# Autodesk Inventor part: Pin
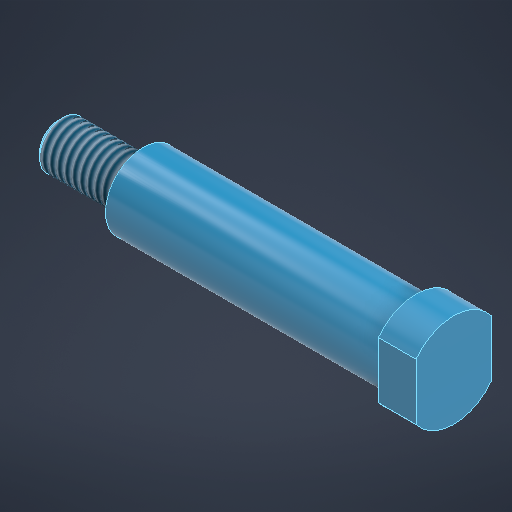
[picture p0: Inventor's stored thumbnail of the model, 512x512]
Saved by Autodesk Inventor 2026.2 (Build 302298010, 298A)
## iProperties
Created: 2021-06
Part Number: Pin
Material: Generic
Document SubType Name: Modeling
Designer: ASUS
Density: 1 g/cm^3
Appearance: Sky Blue Dark
Author: ASUS
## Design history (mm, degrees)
sketch "Sketch1"
  geometry: C1 r 5 at (0, 0); 1 further point
  constraints: 1 centre point, 1 coincident
  dimensions: "d0" = 10 diameter of C1
extrude "Extrusion1" new body sketch "Sketch1" distance "d1" = 4; taper "d2" = 0 deg
sketch "Sketch2"
  geometry: C1 r 4 at (0, 0); 1 further point
  constraints: 1 centre point, 1 coincident
  dimensions: "d3" = 8 diameter of C1
extrude "Extrusion2" join sketch "Sketch2" distance "d4" = 29; taper "d5" = 0 deg
sketch "Sketch3"
  geometry: C1 r 2.5 at (0, 0); 1 further point
  constraints: 1 centre point, 1 coincident
  dimensions: "d6" = 5 diameter of C1
extrude "Extrusion3" join sketch "Sketch3" distance "d7" = 9; taper "d8" = 0 deg
chamfer "Chamfer1" distance "d9" = 0.5; stored, may be unused: second distance "d10" = 2, angle "d11" = 45 deg
sketch "Sketch4"
  geometry: L1 (4, -16.505)-(-4, -16.505); L2 (-4, -16.505)-(-4, 16.505); L3 (-4, 16.505)-(4, 16.505); L4 (4, 16.505)-(4, -16.505); L5 (4, -16.505)-(-4, 16.505); L6 (-4, -16.505)-(4, 16.505); 1 further point
  constraints: 12 end point, 2 midpoint, 2 parallel, 1 horizontal, 1 perpendicular
  dimensions: "d12" = 8 distance of L2.end L3.end
extrude "Extrusion4" sketch "Sketch4" extent not by distance; stored distance "d13" = 0; taper "d14" = 0 deg
thread "Thread1" dims "d15" = 8, "d16" = 0
body "Solid1"
